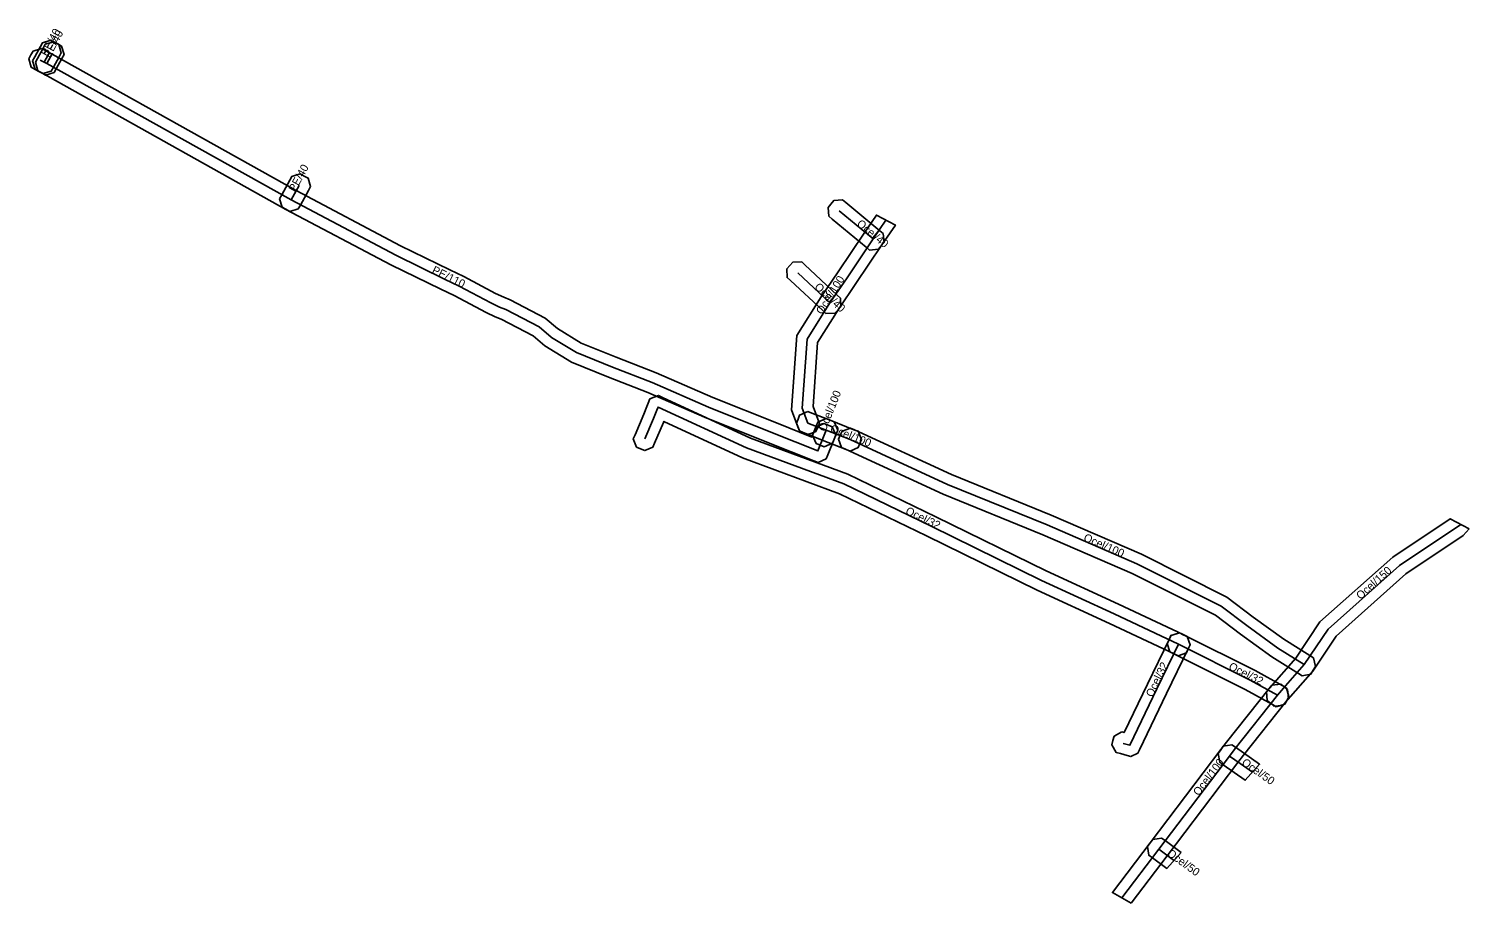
# Model space of a CAD drawing. Extents: x -749621 to -749486, y -967156 to -967074.
import ezdxf

# ---------------------------------------------------------------- set-up
doc = ezdxf.new("R2010")
doc.units = 0
for name, color, linetype in [('Vrstva 1', 7, 'Continuous'), ('Vrstva 14', 7, 'Continuous'), ('Vrstva 18', 7, 'Continuous'), ('Vrstva 20', 7, 'Continuous')]:
    doc.layers.add(name, color=color, linetype=linetype)

msp = doc.modelspace()

# ---------------------------------------------------------------- linework, layer by layer
at = {"layer": 'Vrstva 1'}
for points in [[(-749620.694, -967077.093), (-749620.495, -967076.73), (-749619.962, -967075.759), (-749619.762, -967075.396), (-749618.967, -967075.164), (-749618.604, -967075.363), (-749618.241, -967075.563), (-749618.009, -967076.358), (-749618.208, -967076.721), (-749618.741, -967077.692), (-749618.941, -967078.055), (-749619.736, -967078.287), (-749620.099, -967078.088), (-749620.462, -967077.888)], [(-749619.857, -967075.943), (-749619.493, -967076.141), (-749619.139, -967076.333), (-749618.871, -967076.48), (-749595.983, -967089.271), (-749586.196, -967094.439), (-749581.565, -967096.719), (-749580.262, -967097.336), (-749577.281, -967098.916), (-749576.508, -967099.284), (-749575.921, -967099.521), (-749572.648, -967101.225), (-749571.482, -967102.217), (-749569.259, -967103.573), (-749565.971, -967104.9), (-749562.238, -967106.356), (-749556.934, -967108.677), (-749550.949, -967111.071), (-749547.63, -967112.396), (-749547.408, -967111.841), (-749547.254, -967111.456), (-749546.492, -967111.129), (-749546.108, -967111.283), (-749545.723, -967111.437), (-749545.396, -967112.199), (-749545.55, -967112.583), (-749546.143, -967114.066), (-749546.297, -967114.45), (-749547.058, -967114.777), (-749547.443, -967114.624), (-749551.691, -967112.929), (-749557.706, -967110.523), (-749563.002, -967108.204), (-749566.709, -967106.76), (-749570.161, -967105.367), (-749572.658, -967103.843), (-749573.772, -967102.895), (-749576.759, -967101.339), (-749577.312, -967101.116), (-749578.179, -967100.704), (-749581.158, -967099.124), (-749582.435, -967098.521), (-749587.104, -967096.221), (-749596.937, -967091.029), (-749619.839, -967078.23), (-749620.097, -967078.089), (-749620.447, -967077.899), (-749620.811, -967077.701), (-749621.047, -967076.907), (-749620.849, -967076.543), (-749620.651, -967076.179)], [(-749620.431, -967077.237), (-749620.232, -967076.874), (-749619.699, -967075.903), (-749619.499, -967075.54), (-749618.704, -967075.308), (-749618.341, -967075.507), (-749617.978, -967075.707), (-749617.746, -967076.502), (-749617.945, -967076.865), (-749618.478, -967077.836), (-749618.678, -967078.199), (-749619.473, -967078.431), (-749619.836, -967078.232), (-749620.199, -967078.032)], [(-749597.536, -967090.033), (-749597.337, -967089.67), (-749596.587, -967088.3), (-749596.388, -967087.937), (-749595.593, -967087.704), (-749595.23, -967087.903), (-749594.867, -967088.102), (-749594.634, -967088.897), (-749594.833, -967089.26), (-749595.583, -967090.63), (-749595.782, -967090.993), (-749596.577, -967091.226), (-749596.94, -967091.027), (-749597.303, -967090.828)], [(-749542.219, -967094.844), (-749542.538, -967094.58), (-749545.723, -967091.942), (-749546.042, -967091.678), (-749546.119, -967090.853), (-749545.855, -967090.534), (-749545.591, -967090.215), (-749544.766, -967090.138), (-749544.447, -967090.402), (-749541.262, -967093.04), (-749540.943, -967093.304), (-749540.866, -967094.129), (-749541.13, -967094.448), (-749541.394, -967094.767)], [(-749542.729, -967093.25), (-749541.584, -967091.568), (-749539.805, -967092.51), (-749541.071, -967094.37), (-749543.501, -967098), (-749545.104, -967100.348), (-749547.1, -967103.52), (-749547.517, -967109.54), (-749547.067, -967110.721), (-749546.92, -967111.108), (-749547.259, -967111.865), (-749547.646, -967112.012), (-749548.033, -967112.159), (-749548.79, -967111.82), (-749548.937, -967111.433), (-749549.543, -967109.84), (-749549.06, -967102.88), (-749546.776, -967099.252), (-749545.159, -967096.88)], [(-749548.587, -967095.965), (-749548.284, -967096.247), (-749545.258, -967099.069), (-749544.955, -967099.351), (-749544.927, -967100.179), (-749545.209, -967100.482), (-749545.491, -967100.785), (-749546.319, -967100.813), (-749546.622, -967100.531), (-749549.648, -967097.709), (-749549.951, -967097.427), (-749549.979, -967096.599), (-749549.697, -967096.296), (-749549.415, -967095.993)], [(-749554.144, -967114.334), (-749561.51, -967110.931), (-749561.545, -967111.02), (-749562.376, -967112.966), (-749562.539, -967113.347), (-749563.308, -967113.656), (-749563.689, -967113.493), (-749564.07, -967113.33), (-749564.379, -967112.561), (-749564.216, -967112.18), (-749563.395, -967110.26), (-749563.099, -967109.511), (-749562.978, -967109.209), (-749562.819, -967108.81), (-749562.42, -967108.651), (-749562.021, -967108.492), (-749561.631, -967108.672), (-749553.376, -967112.486), (-749544.257, -967115.869), (-749536.022, -967119.861), (-749525.671, -967124.937), (-749518.877, -967128.064), (-749512.823, -967130.926), (-749512.449, -967131.103), (-749512.169, -967131.883), (-749512.346, -967132.257), (-749512.523, -967132.631), (-749513.303, -967132.911), (-749513.677, -967132.734), (-749519.723, -967129.876), (-749526.529, -967126.743), (-749536.898, -967121.659), (-749545.043, -967117.711)], [(-749548.024, -967109.995), (-749547.638, -967110.145), (-749545.925, -967110.814), (-749543.691, -967111.699), (-749543.306, -967111.851), (-749542.977, -967112.612), (-749543.129, -967112.997), (-749543.281, -967113.382), (-749544.042, -967113.711), (-749544.427, -967113.559), (-749546.657, -967112.676), (-749548.366, -967112.009), (-749548.752, -967111.858), (-749549.084, -967111.099), (-749548.934, -967110.713), (-749548.783, -967110.327)], [(-749547.562, -967112.223), (-749547.407, -967111.839), (-749547.219, -967111.372), (-749547.064, -967110.988), (-749546.302, -967110.662), (-749545.918, -967110.817), (-749545.534, -967110.972), (-749545.208, -967111.734), (-749545.363, -967112.118), (-749545.551, -967112.585), (-749545.706, -967112.969), (-749546.468, -967113.295), (-749546.852, -967113.14), (-749547.236, -967112.985)], [(-749501.663, -967134.807), (-749502.013, -967134.586), (-749504.5, -967133.019), (-749507.457, -967130.882), (-749509.782, -967129.102), (-749517.593, -967125.196), (-749525.978, -967121.552), (-749535.328, -967117.748), (-749544.477, -967113.537), (-749544.853, -967113.364), (-749545.14, -967112.587), (-749544.967, -967112.211), (-749544.794, -967111.835), (-749544.017, -967111.548), (-749543.641, -967111.721), (-749534.532, -967115.912), (-749525.202, -967119.708), (-749516.747, -967123.384), (-749508.718, -967127.398), (-749506.263, -967129.278), (-749503.38, -967131.361), (-749500.947, -967132.894), (-749500.597, -967133.115), (-749500.413, -967133.923), (-749500.634, -967134.273), (-749500.855, -967134.623)], [(-749486.011, -967121.007), (-749486.569, -967121.634), (-749491.946, -967125.232), (-749498.48, -967131.062), (-749500.685, -967134.349), (-749503.226, -967137.267), (-749503.498, -967137.579), (-749504.325, -967137.636), (-749504.637, -967137.364), (-749504.949, -967137.092), (-749505.006, -967136.265), (-749504.734, -967135.953), (-749502.275, -967133.131), (-749500, -967129.738), (-749493.174, -967123.648), (-749487.806, -967120.056)], [(-749518.586, -967140.053), (-749518.361, -967140.115), (-749516.18, -967135.565), (-749514.149, -967131.392), (-749513.968, -967131.02), (-749513.184, -967130.75), (-749512.812, -967130.931), (-749512.44, -967131.112), (-749512.17, -967131.896), (-749512.351, -967132.268), (-749514.38, -967136.435), (-749516.918, -967141.732), (-749517.075, -967142.059), (-749517.734, -967142.36), (-749518.084, -967142.264), (-749518.715, -967142.091), (-749519.115, -967141.982), (-749519.525, -967141.262), (-749519.415, -967140.863), (-749519.306, -967140.463)], [(-749504.101, -967137.685), (-749504.464, -967137.485), (-749507.016, -967136.075), (-749513.698, -967132.724), (-749514.068, -967132.538), (-749514.33, -967131.752), (-749514.144, -967131.382), (-749513.958, -967131.012), (-749513.172, -967130.75), (-749512.802, -967130.936), (-749506.084, -967134.305), (-749503.496, -967135.735), (-749503.134, -967135.935), (-749502.905, -967136.731), (-749503.105, -967137.094), (-749503.305, -967137.456)], [(-749517.696, -967156.122), (-749519.455, -967155.132), (-749515.917, -967150.456), (-749509.284, -967141.711), (-749508.75, -967141.007), (-749504.763, -967135.988), (-749504.505, -967135.664), (-749503.682, -967135.569), (-749503.358, -967135.827), (-749503.034, -967136.085), (-749502.939, -967136.908), (-749503.197, -967137.232), (-749507.17, -967142.233), (-749507.69, -967142.919), (-749514.323, -967151.664)], [(-749507.91, -967141.498), (-749505.662, -967143.087), (-749507, -967144.59), (-749509.064, -967143.132), (-749509.402, -967142.893), (-749509.543, -967142.076), (-749509.304, -967141.738), (-749509.065, -967141.4), (-749508.248, -967141.259)], [(-749513.024, -967151.358), (-749514.359, -967152.858), (-749515.711, -967151.866), (-749516.045, -967151.621), (-749516.171, -967150.803), (-749515.926, -967150.469), (-749515.681, -967150.135), (-749514.863, -967150.009), (-749514.529, -967150.254)]]:
    msp.add_lwpolyline(points, close=True, dxfattribs=at)
at = {"layer": 'Vrstva 14'}
for p, q in [((-749619.618, -967077.211), (-749619.085, -967076.24)), ((-749619.355, -967077.355), (-749618.822, -967076.384)), ((-749596.46, -967090.15), (-749595.71, -967088.78)), ((-749541.9, -967093.81), (-749545.085, -967091.172)), ((-749548.966, -967096.978), (-749545.94, -967099.8)), ((-749546.479, -967112.212), (-749546.291, -967111.745))]:
    msp.add_line(p, q, dxfattribs=at)
for points in [[(-749619.97, -967077.02), (-749619.618, -967077.211), (-749619.355, -967077.355), (-749596.46, -967090.15), (-749586.65, -967095.33), (-749582, -967097.62), (-749580.71, -967098.23), (-749577.73, -967099.81), (-749576.91, -967100.2), (-749576.34, -967100.43), (-749573.21, -967102.06), (-749572.07, -967103.03), (-749572.053, -967103.039), (-749569.71, -967104.47), (-749566.34, -967105.83), (-749562.62, -967107.28), (-749557.32, -967109.6), (-749551.32, -967112), (-749547.072, -967113.695), (-749546.479, -967112.212)], [(-749540.695, -967092.039), (-749541.9, -967093.81), (-749544.33, -967097.44), (-749545.94, -967099.8), (-749548.08, -967103.2), (-749548.53, -967109.69), (-749548.002, -967111.077)], [(-749513.25, -967131.83), (-749519.3, -967128.97), (-749526.1, -967125.84), (-749536.46, -967120.76), (-749544.65, -967116.79), (-749553.76, -967113.41), (-749562.05, -967109.58), (-749562.17, -967109.88), (-749562.47, -967110.64), (-749563.296, -967112.573)], [(-749548.002, -967111.077), (-749546.291, -967111.745), (-749544.059, -967112.629)], [(-749501.48, -967133.74), (-749503.94, -967132.19), (-749506.86, -967130.08), (-749509.25, -967128.25), (-749517.17, -967124.29), (-749525.59, -967120.63), (-749534.93, -967116.83), (-749544.059, -967112.629)], [(-749503.98, -967136.61), (-749503.224, -967135.742), (-749501.48, -967133.74), (-749499.24, -967130.4), (-749492.56, -967124.44), (-749486.803, -967120.588)], [(-749513.25, -967131.83), (-749515.28, -967136), (-749517.82, -967141.3), (-749518.451, -967141.127)], [(-749503.98, -967136.61), (-749506.55, -967135.19), (-749513.25, -967131.83)], [(-749503.98, -967136.61), (-749507.96, -967141.62), (-749508.487, -967142.315), (-749515.12, -967151.06), (-749518.575, -967155.627)], [(-749515.12, -967151.06), (-749513.741, -967152.07), (-749513.69, -967152.107)]]:
    msp.add_lwpolyline(points, dxfattribs=at)
at = {"layer": 'Vrstva 18'}
msp.add_lwpolyline([(-749506.331, -967143.838), (-749507.481, -967143.025), (-749508.487, -967142.315)], dxfattribs=at)

# ---------------------------------------------------------------- texts
at = {"layer": 'Vrstva 20'}
for s, rotation, p in [('PE/40', 61.23679, (-749619.352, -967076.725)), ('PE/40', 61.23679, (-749619.089, -967076.869)), ('PE/40', 61.30171, (-749596.085, -967089.465)), ('Ocel/40', 320.36649, (-749543.492, -967092.491)), ('PE/110', 333.78099, (-749583.322, -967096.969)), ('Ocel/40', 316.99788, (-749547.453, -967098.389)), ('Ocel/100', 57.81321, (-749546.67, -967100.959)), ('Ocel/100', 68.07178, (-749546.367, -967111.932)), ('Ocel/100', 338.39359, (-749545.982, -967111.867)), ('Ocel/32', 334.13879, (-749538.924, -967119.565)), ('Ocel/100', 336.50641, (-749522.232, -967122.09)), ('Ocel/150', 41.73984, (-749496.199, -967127.686)), ('Ocel/32', 64.39415, (-749515.689, -967136.854)), ('Ocel/32', 333.36658, (-749508.632, -967134.146)), ('Ocel/100', 52.82003, (-749511.367, -967146.112)), ('Ocel/50', 324.73917, (-749507.408, -967143.076)), ('Ocel/50', 323.7804, (-749514.405, -967151.583))]:
    msp.add_text(s, height=0.75, rotation=rotation, dxfattribs=at).set_placement(p)

doc.saveas('drawing.dxf')
